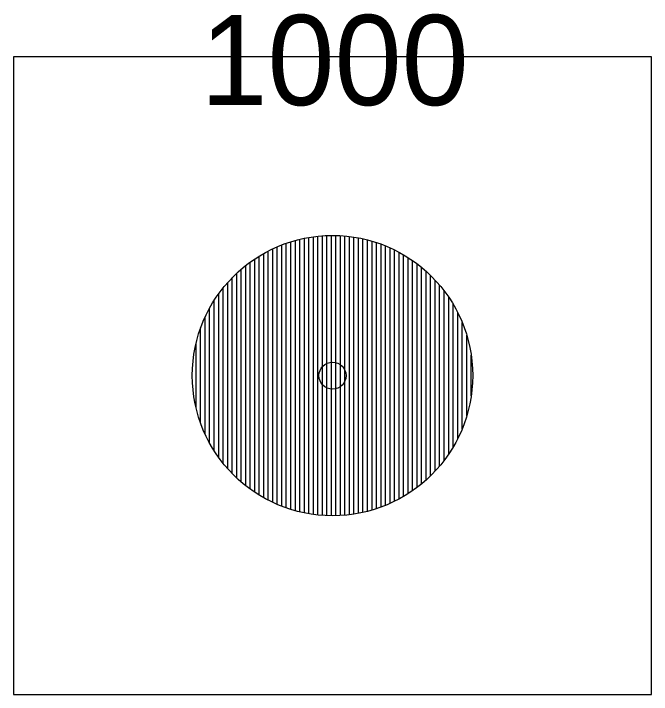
# Model space of a CAD drawing. Extents: x 1968123 to 1968241, y 796379 to 796709.
# Drawn here: x 1968182.96 to 1968190.03, y 796517.76 to 796525.31 of the extents above; entities that cross this region are included whole.
import ezdxf

# ---------------------------------------------------------------- set-up
doc = ezdxf.new("R2010")
doc.units = 0
for name, color, linetype in [('RD_HC_Survey', 7, 'Continuous'), ('RD_HC_Survey_txCode', 7, 'Continuous'), ('RD_SMD_Locator', 7, 'Continuous')]:
    doc.layers.add(name, color=color, linetype=linetype)

msp = doc.modelspace()

# ---------------------------------------------------------------- linework, layer by layer
at = {"layer": 'RD_HC_Survey'}
for p, q in [((1968186.2291, 796519.7583), (1968186.2291, 796522.8231)), ((1968186.2791, 796519.7506), (1968186.2791, 796522.8308)), ((1968186.3291, 796519.7446), (1968186.3291, 796522.8368)), ((1968186.3791, 796519.7401), (1968186.3791, 796522.8413)), ((1968186.4291, 796519.7373), (1968186.4291, 796522.8441)), ((1968186.4791, 796519.7362), (1968186.4791, 796522.8452)), ((1968186.5291, 796519.7366), (1968186.5291, 796522.8448)), ((1968186.5791, 796519.7386), (1968186.5791, 796522.8428)), ((1968186.6291, 796519.7423), (1968186.6291, 796522.8391)), ((1968186.6791, 796519.7475), (1968186.6791, 796522.8339)), ((1968186.7291, 796519.7545), (1968186.7291, 796522.8269)), ((1968185.9791, 796519.8228), (1968185.9791, 796522.7586)), ((1968186.0291, 796519.8063), (1968186.0291, 796522.7751)), ((1968186.0791, 796519.7917), (1968186.0791, 796522.7897)), ((1968186.1291, 796519.7788), (1968186.1291, 796522.8026)), ((1968186.1791, 796519.7677), (1968186.1791, 796522.8137)), ((1968186.7791, 796519.763), (1968186.7791, 796522.8184)), ((1968186.8291, 796519.7733), (1968186.8291, 796522.8081)), ((1968186.8791, 796519.7853), (1968186.8791, 796522.7961)), ((1968186.9291, 796519.7991), (1968186.9291, 796522.7823)), ((1968186.9791, 796519.8147), (1968186.9791, 796522.7667)), ((1968187.0291, 796519.8322), (1968187.0291, 796522.7492)), ((1968185.7791, 796519.9087), (1968185.7791, 796522.6727)), ((1968185.8291, 796519.8841), (1968185.8291, 796522.6973)), ((1968185.8791, 796519.8616), (1968185.8791, 796522.7198)), ((1968185.9291, 796519.8412), (1968185.9291, 796522.7402)), ((1968187.0791, 796519.8516), (1968187.0791, 796522.7298)), ((1968187.1291, 796519.8731), (1968187.1291, 796522.7083)), ((1968187.1791, 796519.8967), (1968187.1791, 796522.6847)), ((1968185.6791, 796519.965), (1968185.6791, 796522.6164)), ((1968185.7291, 796519.9356), (1968185.7291, 796522.6458)), ((1968187.2291, 796519.9225), (1968187.2291, 796522.6589)), ((1968187.2791, 796519.9507), (1968187.2791, 796522.6307)), ((1968187.3291, 796519.9814), (1968187.3291, 796522.6)), ((1968185.5791, 796520.0317), (1968185.5791, 796522.5497)), ((1968185.6291, 796519.9969), (1968185.6291, 796522.5845)), ((1968187.3791, 796520.0148), (1968187.3791, 796522.5666)), ((1968187.4291, 796520.0511), (1968187.4291, 796522.5303)), ((1968185.4791, 796520.1105), (1968185.4791, 796522.4709)), ((1968185.5291, 796520.0694), (1968185.5291, 796522.512)), ((1968187.4791, 796520.0905), (1968187.4791, 796522.4909)), ((1968187.5291, 796520.1335), (1968187.5291, 796522.4479)), ((1968185.3791, 796520.2042), (1968185.3791, 796522.3772)), ((1968185.4291, 796520.1553), (1968185.4291, 796522.4261)), ((1968187.5791, 796520.1804), (1968187.5791, 796522.401)), ((1968185.3291, 796520.2579), (1968185.3291, 796522.3235)), ((1968187.6291, 796520.2317), (1968187.6291, 796522.3497)), ((1968187.6791, 796520.2881), (1968187.6791, 796522.2933)), ((1968185.2791, 796520.317), (1968185.2791, 796522.2644)), ((1968187.7291, 796520.3506), (1968187.7291, 796522.2308)), ((1968185.2291, 796520.3828), (1968185.2291, 796522.1986)), ((1968187.7791, 796520.4203), (1968187.7791, 796522.1611)), ((1968185.1791, 796520.4566), (1968185.1791, 796522.1248)), ((1968187.8291, 796520.4994), (1968187.8291, 796522.082)), ((1968185.1291, 796520.541), (1968185.1291, 796522.0404)), ((1968187.8791, 796520.5908), (1968187.8791, 796521.9906)), ((1968185.0791, 796520.6401), (1968185.0791, 796521.9413)), ((1968187.9291, 796520.7003), (1968187.9291, 796521.8811)), ((1968185.0291, 796520.7619), (1968185.0291, 796521.8195)), ((1968187.9791, 796520.8409), (1968187.9791, 796521.7405)), ((1968184.9791, 796520.9289), (1968184.9791, 796521.6525)), ((1968188.0291, 796521.0649), (1968188.0291, 796521.5165))]:
    msp.add_line(p, q, dxfattribs=at)
msp.add_lwpolyline([(1968190.0265, 796524.8262), (1968182.9555, 796524.8262), (1968182.9555, 796517.7552), (1968190.0265, 796517.7552)], close=True, dxfattribs=at)
msp.add_circle((1968186.491, 796521.2907), 1.5546, dxfattribs=at)
at = {"layer": 'RD_SMD_Locator'}
msp.add_circle((1968186.491, 796521.2907), 0.15, dxfattribs=at)

# ---------------------------------------------------------------- texts
at = {"layer": 'RD_HC_Survey_txCode'}
msp.add_text('1000', height=1, dxfattribs=at).set_placement((1968185.0264, 796524.2907))

doc.saveas('drawing.dxf')
